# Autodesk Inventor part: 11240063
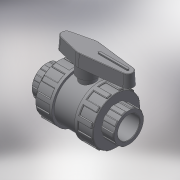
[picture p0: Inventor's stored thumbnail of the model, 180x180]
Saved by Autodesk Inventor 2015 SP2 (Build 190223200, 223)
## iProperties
Created: 2017-11
Part Number: 11240063
Material: Generic
Description: PLASSON BI STOP VALVE CEM PVC 63
Document SubType Name: Modeling
Designer: KIM
Density: 1 g/cm^3
Appearance: Default
Author: KIM
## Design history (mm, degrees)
derived "112400 - 112700.ipt"
feature "Solid1::112400 - 112700.ipt"
tag "TaggingFeature1"
body "Solid1"
other parameters: "d0" = 169, "d1" = 63, "d2" = 118, "d3" = 38, "d4" = 50.4, "d5" = 26.6, "d7" = 88.2, "d8" = 106.2, "d13" = 1.89, "d23" = 38, "d24" = 113.28, "d25" = 1.26, "d26" = 1.89, "d27" = 17.7, "d28" = 8.85, "d29" = 28.5, "d30" = 0, "d35" = 1.89, "d39" = 59, "d45" = 360 deg, "d47" = 1.26, "d50" = 64.9, "d51" = 35.4, "d53" = 0, "d55" = 12.6, "d56" = 6.3, "d57" = 26.6, "d58" = 0, "d59" = 1.89, "d61" = 360 deg, "d63" = 47.2, "d64" = 106, "d66" = 129, "d68" = 23.6, "d69" = 38.7, "d70" = 26.5, "d71" = 3 deg, "d73" = 2.36, "d74" = 51.6, "d75" = 3.18, "d76" = 0, "d77" = 1.26, "d_" = 63, "l_" = 38, "H_" = 169, "K_" = 118, "F_" = 106, "J_" = 129, "d67" = 47.2, "d72" = 11.8
